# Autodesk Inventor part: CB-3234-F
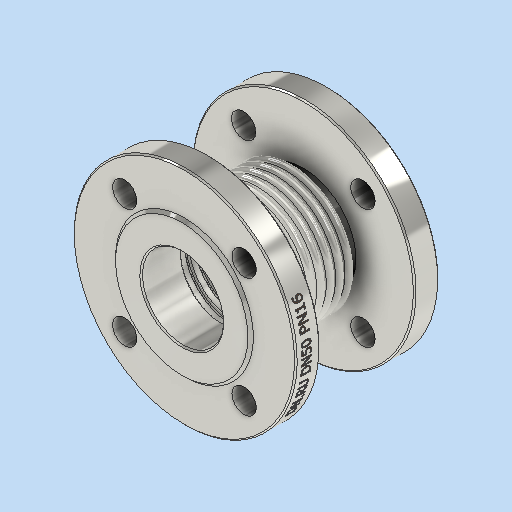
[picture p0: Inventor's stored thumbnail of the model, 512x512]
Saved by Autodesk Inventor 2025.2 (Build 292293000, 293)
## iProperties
Company: DN.RU
Created: 2026-04
Part Number: CB-3234-F
Material: Типовые
Document SubType Name: Modeling
Designer: DN.RU
Density: 6.53951 g/cm^3
Appearance: По умолчанию
Description: D140-02113
Mass: 5000 g
Surface Area: 2213.38 cm^2
Volume: 764.583 cm^3
Author: DN.RU
Title: Компенсатор сильфонный осевой DN.ru Ду50 Ру16
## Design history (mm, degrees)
sketch "Эскиз1"
  geometry: L1 (0, 0)-(0, -55); L2 (36, -55)-(36, 0); L3 (36, 0)-(0, 0); L4 (36, 0)-(36, -3.5); L5 (28, -3.5)-(44, -3.5); L6 (28, -6)-(44, -6); L7 (44, -1)-(28, -1); L8 (44, -4)-(28, -4); L9 (28, -3)-(44, -3); L10 (44, -8)-(28, -8); L11 (28, -10)-(44, -10); L12 (28, -10.5)-(44, -10.5); L13 (28, -13)-(44, -13); L14 (44, -11)-(28, -11); L15 (44, -15)-(28, -15); L16 (28, -17)-(44, -17); L17 (28, -17.5)-(44, -17.5); L18 (28, -20)-(44, -20); L19 (44, -18)-(28, -18); L20 (44, -22)-(28, -22); L21 (28, -24)-(44, -24); L22 (28, -24.5)-(44, -24.5); L23 (28, -27)-(44, -27); L24 (44, -25)-(28, -25); L25 (0, -55)-(36, -55); L26 (36, -55)-(30, -55); L27 (36, -22)-(34, -22); L28 (30, -55)-(30, -25); L29 (36, -24)-(34, -24); L30 (34, -24)-(34, -18); L31 (36, -17)-(34, -17); L32 (34, -17)-(34, -11); L33 (36, -10)-(34, -10); L34 (34, -10)-(34, -4); L35 (36, -3)-(35, -3); L36 (35, -3)-(34, 0); L37 (0, -55)-(0, -35); L38 (0, -35)-(82.5, -35); L39 (82.5, -35)-(82.5, -55); L40 (82.5, -55)-(0, -55); L41 (36, -35)-(36, -45); L42 (36, -45)-(39, -45); L43 (39, -45)-(39, -35); L44 (39, -35)-(36, -35); A1 r 2.5 centre (28, -3.5) between (28, -1) and (28, -6); A2 r 2.5 centre (44, -3.5) between (44, -6) and (44, -1); A3 r 0.5 centre (28, -3.5) between (28, -3) and (28, -4); A4 r 0.5 centre (44, -3.5) between (44, -4) and (44, -3); A5 r 0.5 centre (28, -10.5) between (28, -10) and (28, -11); A6 r 2.5 centre (28, -10.5) between (28, -8) and (28, -13); A7 r 0.5 centre (44, -10.5) between (44, -11) and (44, -10); A8 r 2.5 centre (44, -10.5) between (44, -13) and (44, -8); A9 r 0.5 centre (28, -17.5) between (28, -17) and (28, -18); A10 r 2.5 centre (28, -17.5) between (28, -15) and (28, -20); A11 r 0.5 centre (44, -17.5) between (44, -18) and (44, -17); A12 r 2.5 centre (44, -17.5) between (44, -20) and (44, -15); A13 r 0.5 centre (28, -24.5) between (28, -24) and (28, -25); A14 r 2.5 centre (28, -24.5) between (28, -22) and (28, -27); A15 r 0.5 centre (44, -24.5) between (44, -25) and (44, -24); A16 r 2.5 centre (44, -24.5) between (44, -27) and (44, -22); 20 further points
  constraints: 96 end point, 32 point on circle, 19 point on line, 16 centre point, 7 parallel, 7 perpendicular, 6 midpoint, 4 tangent, 2 vertical, 1 horizontal, 69 other
  dimensions: "d0" = 55 distance of L1.start L1.end; "d3" = 3.5 distance of L2.end L4.end; "d4" = 8 distance of L4.end L5.end; "d5" = 5 diameter of A2; "d6" = 2 distance between parallel lines of L6 L8; "d9" = 7 distance of L4.end point (36, -10.5); "d15" = 2 distance of L27.start L27.end; "d16" = 2 distance of L29.start L29.end; "d17" = 2 distance of L31.start L31.end; "d18" = 2 distance of L33.start L33.end; "d19" = 1 distance of L35.start L35.end; "d27" = 30 distance between parallel lines of L1 L28; "d28" = 6 distance between parallel lines of L2 L28; "d29" = 20 distance of L1.end L37.end; "d30" = 82.5 distance of L37.end L38.end; "d31" = 10 distance of L41.start L41.end; "d32" = 3 distance of L42.end L41.end
revolve "Вращение1" sketch "Эскиз1" stored, may be unused: angle "d20" = 360 deg
sketch "Эскиз3" dims "d33" = 125
  geometry: L1 (0, 0)-(54.414, 54.414); L2 (0, 0)-(76.954, 0); C1 r 9 at (44.194, 44.194); C2 r 9 at (-44.194, 44.194); C3 r 9 at (-44.194, -44.194); C4 r 9 at (44.194, -44.194); C5 r 30 at (0, 0) reference; C6 r 51 at (0, 0); C7 r 82.5 at (0, 0) reference; 1 further point
  constraints: 5 centre point, 4 end point, 2 coincident, 1 equal length, 1 horizontal, 1 point on line, 12 other
  dimensions: "d34" = 45 deg angle of L2 L1; "d35" = 18 diameter of C1; "d38" = 360 deg dimension on point (0, 0) C1.centre (derived); "d40" = 102 diameter of C6
  node "Эскиз — круговой массив1" dims "d38" = 360 deg (derived)
extrude "Выдавливание1" cut sketch "Эскиз3" stored distance "d41" = 10; taper "d42" = 0 deg
extrude "Выдавливание2" cut sketch "Эскиз3" distance "d43" = 2; taper "d44" = 0 deg
chamfer "Фаска2" distance "d45" = 2; stored, may be unused: second distance "d46" = 2, angle "d47" = 45 deg
chamfer "Фаска3" distance "d48" = 1; stored, may be unused: second distance "d49" = 2, angle "d50" = 45 deg
mirror "Зеркальное отражение2"
fillet "Сопряжение2" dims "d51" = 1
node "РабПлоскость2"
sketch "Эскиз4"
  geometry: L1 (-44.383, 3.589)-(46.395, 3.589); L2 (46.395, 3.589)-(46.395, 0.413); L3 (46.395, 0.413)-(-44.383, 0.413); L4 (-44.383, 0.413)-(-44.383, 3.589); 1 further point
  constraints: 2 other
feature "Рельеф2" sketch "Эскиз4" dims "d52" = 0.1, "d53" = 0
node "Твердое тело1"
node "Эскиз — прямоугольный массив1" dims "d9" = 7, "d12" = 10
